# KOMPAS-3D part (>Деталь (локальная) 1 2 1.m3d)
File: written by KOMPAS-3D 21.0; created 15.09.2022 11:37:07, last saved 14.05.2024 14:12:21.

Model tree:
1. Эскиз:1

Referenced files in C:\Program Files\Ascon\Libs\EasySteel\: Rolled metal.kle, StandartSolutions.kle, DSTVProperties.lpt
Referenced files in W:\Шаблоны чертежей\: Констр. чертеж А3 гориз. перв. лист.cdt
Referenced files in C:\Program Files\Ascon\Libs\EasySteel\BeltEndings\: 
Referenced files in C:\Program Files\Ascon\Libs\EasySteel\Punctures\: 
Referenced files in C:\Program Files\Ascon\Libs\EasySteel\Insulations\: 
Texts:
  Уголок равнополочный по ГОСТ 8509-93 (Спец)
  config2DpacketName
  config2DstdSizeID
  Констр. чертеж А3 гориз. перв. лист.cdt
  Болт ГОСТ 22353-77
  Шайба ГОСТ 22355-77
  Гайка ГОСТ 22354-77
  Нормальная пружинная шайба ГОСТ 6402-70 (исп. 1)
  SeaRox SL 436
  Сталь 09Г2С ГОСТ 19281-2014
